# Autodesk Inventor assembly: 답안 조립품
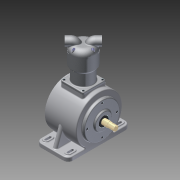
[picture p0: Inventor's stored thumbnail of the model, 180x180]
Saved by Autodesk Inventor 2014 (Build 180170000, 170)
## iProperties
Created: 2015-06
Part Number: 답안 조립품
Document SubType Name: Assembly
Designer: SEC
Author: SEC
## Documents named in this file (15)
- C:\Documents and Settings\SEC\바탕 화면\450605V1001\답안 조립품.iam
- C:\Documents and Settings\SEC\바탕 화면\450605V1001\본체.ipt
- C:\Documents and Settings\SEC\바탕 화면\450605V1001\베어링 6204.ipt
- C:\Documents and Settings\SEC\바탕 화면\450605V1001\크랭크 서브축.ipt
- C:\Documents and Settings\SEC\바탕 화면\450605V1001\베어링 NA 4902.ipt
- C:\Documents and Settings\SEC\바탕 화면\450605V1001\커넥팅 로드.ipt
- C:\Documents and Settings\SEC\바탕 화면\450605V1001\메인 크랭크 축-구동부.ipt
- C:\Documents and Settings\SEC\바탕 화면\450605V1001\피스톤 핀.ipt
- C:\Documents and Settings\SEC\바탕 화면\450605V1001\피스톤.ipt
- C:\Documents and Settings\SEC\바탕 화면\450605V1001\실린더.ipt
- C:\Documents and Settings\SEC\바탕 화면\450605V1001\메인커버.ipt
- C:\Documents and Settings\SEC\바탕 화면\450605V1001\오일실.ipt
- C:\Documents and Settings\SEC\바탕 화면\450605V1001\M4x0.7.ipt
- C:\Documents and Settings\SEC\바탕 화면\450605V1001\실린더헤드.ipt
- C:\Documents and Settings\SEC\바탕 화면\450605V1001\M5x0.8.ipt
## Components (14 placed, 4 different names)
1. 피스톤 핀:1
2. 피스톤:1
3. M4x0.7:1
4. M4x0.7:3
5. M4x0.7:4
6. M4x0.7:5
7. M4x0.7:2
8. M4x0.7:6
9. M4x0.7:7
10. M4x0.7:8
11. M5x0.8:1
12. M5x0.8:2
13. M5x0.8:3
14. M5x0.8:4
